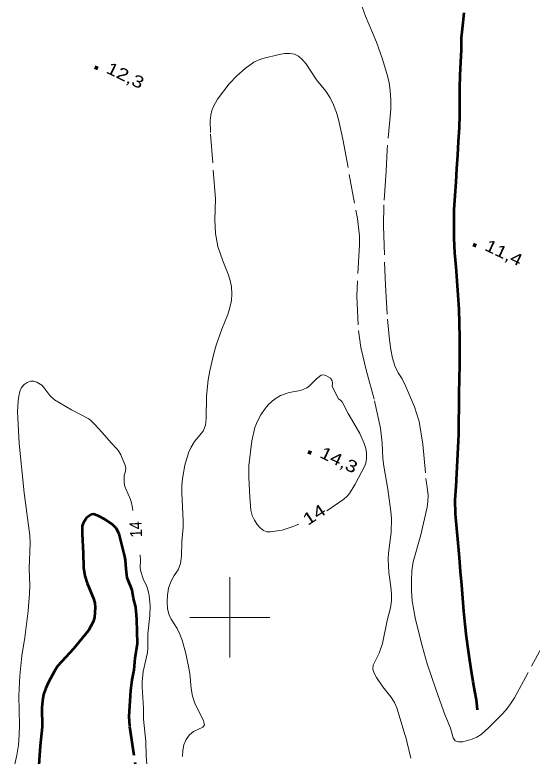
# Model space of a CAD drawing. Extents: x 355726 to 357533, y 5103782 to 5105258.
# Drawn here: x 356273.2 to 356337.7, y 5104282.7 to 5104375.1 of the extents above; entities that cross this region are included whole.
import ezdxf
from ezdxf.enums import TextEntityAlignment as Align

# ---------------------------------------------------------------- set-up
doc = ezdxf.new("R2010")
doc.units = 0
doc.header["$LTSCALE"] = 0.6
doc.linetypes.add('DASH_DOUBLE_DOT', pattern=[9.2, 5, -1.2, 0.3, -1.2, 0.3, -1.2])
doc.linetypes.add('LONG_DASHED', pattern=[7.5, 6, -1.5])
for name, color, linetype, lineweight in [('1', 7, 'LONG_DASHED', 53), ('2', 7, 'LONG_DASHED', 13), ('3', 7, 'Continuous', 140), ('4', 7, 'DASH_DOUBLE_DOT', 53), ('61', 7, 'Continuous', 13)]:
    doc.layers.add(name, color=color, linetype=linetype, lineweight=lineweight)

msp = doc.modelspace()

# ---------------------------------------------------------------- linework, layer by layer
at = {"layer": '1'}
msp.add_lwpolyline([(356288.76, 5104278.34), (356287.53, 5104286.45), (356287.46, 5104287.66), (356287.66, 5104290.91), (356287.84, 5104292.21), (356288.09, 5104293.46), (356288.22, 5104294.91), (356288.47, 5104296.76), (356288.42, 5104299.73), (356288.3, 5104301.28), (356287.98, 5104302.36), (356287.81, 5104303.38), (356287.22, 5104304.95), (356287.06, 5104306.05), (356287, 5104307.12), (356286.93, 5104307.59), (356286.2, 5104310.44), (356285.82, 5104311.13), (356285.33, 5104311.61), (356284.38, 5104312.25), (356283.58, 5104312.68), (356283, 5104312.88), (356282.72, 5104312.83), (356282.13, 5104312.41), (356281.71, 5104311.75), (356281.6, 5104311.38), (356281.57, 5104310.4), (356281.71, 5104308), (356281.74, 5104306.22), (356281.94, 5104305.18), (356282.22, 5104304.26), (356283.02, 5104302.34), (356283.15, 5104301.82), (356283.22, 5104301.24), (356283.12, 5104300.01), (356282.95, 5104299.43), (356282.36, 5104298.38), (356280.5, 5104296.09), (356278.52, 5104293.94), (356278.12, 5104293.32), (356277.37, 5104291.94), (356277.04, 5104291.19), (356276.78, 5104290.4), (356276.63, 5104289.59), (356276.57, 5104288.74), (356276.6, 5104286.38), (356276.37, 5104284), (356275.85, 5104277.04)], dxfattribs=at)
at = {"layer": '2'}
for points in [[(356316.53, 5104376.09), (356316.91, 5104374.96), (356318.28, 5104371.69), (356319.03, 5104369.59), (356319.62, 5104367.63), (356319.86, 5104366.67), (356320.02, 5104365.63), (356320.1, 5104364.53), (356320.08, 5104363.34), (356319.61, 5104358.26), (356319.5, 5104355.61), (356319.22, 5104351.44), (356319.16, 5104348.8), (356319.41, 5104341.4), (356319.65, 5104337.17), (356319.92, 5104334.59), (356320.09, 5104333.41), (356320.31, 5104332.33), (356320.6, 5104331.36), (356321.02, 5104330.5), (356321.49, 5104329.73), (356321.93, 5104328.88), (356323.03, 5104326.24), (356323.61, 5104324.43), (356324.08, 5104321.61), (356324.47, 5104317.32), (356324.68, 5104315.92), (356324.74, 5104315.2), (356324.72, 5104314.47), (356324.6, 5104313.74), (356323.82, 5104310.3), (356322.89, 5104306.93), (356322.71, 5104305.8)], [(356294.12, 5104282.68), (356294.15, 5104283.4), (356294.29, 5104284.13), (356294.57, 5104284.79), (356294.96, 5104285.37), (356295.48, 5104285.8), (356296.62, 5104286.3), (356296.83, 5104286.63), (356296.72, 5104287.13), (356295.64, 5104289.32), (356295.35, 5104290.2), (356295.18, 5104291.16), (356295, 5104293.03), (356294.86, 5104293.88), (356294.51, 5104295.51), (356294.06, 5104297.15), (356293.78, 5104297.93), (356293.45, 5104298.63), (356292.69, 5104299.8), (356292.4, 5104300.41), (356292.25, 5104301.13), (356292.19, 5104301.93), (356292.24, 5104302.76), (356292.36, 5104303.63), (356292.64, 5104304.44), (356293.05, 5104305.21), (356293.55, 5104305.93), (356293.86, 5104306.74), (356293.96, 5104307.63), (356294.04, 5104309.46), (356294.19, 5104311.19), (356294.2, 5104312.03), (356294, 5104315.55), (356294, 5104316.44), (356294.1, 5104317.3), (356294.41, 5104318.97), (356294.86, 5104320.5), (356295.18, 5104321.24), (356295.62, 5104321.93), (356296.66, 5104323.21), (356296.98, 5104323.96), (356297.05, 5104324.8), (356297.09, 5104327.59), (356297.32, 5104329.63), (356297.52, 5104330.74), (356298.02, 5104332.9), (356298.32, 5104333.93), (356299.02, 5104335.94), (356299.74, 5104337.74), (356300.01, 5104338.62), (356300.21, 5104339.49), (356300.26, 5104340.33), (356300.22, 5104341.19), (356300.05, 5104342.01), (356299.81, 5104342.8), (356299.13, 5104344.43), (356298.52, 5104346.22), (356298.2, 5104347.86), (356298.15, 5104349.55), (356298.21, 5104352.17), (356297.6, 5104360.43), (356297.57, 5104361.93), (356297.62, 5104362.59), (356297.76, 5104363.18), (356297.97, 5104363.7), (356298.45, 5104364.59), (356299.91, 5104366.5), (356300.86, 5104367.49), (356301.93, 5104368.43), (356302.98, 5104369.21), (356303.53, 5104369.47), (356304.14, 5104369.68), (356306.17, 5104370.18), (356306.84, 5104370.28), (356307.47, 5104370.3)], [(356307.47, 5104370.3), (356308.06, 5104370.22), (356308.57, 5104369.97), (356309.04, 5104369.55), (356309.48, 5104369.04), (356310.82, 5104367.01), (356312, 5104365.59), (356312.51, 5104364.76), (356312.95, 5104363.88), (356313.32, 5104362.93), (356313.61, 5104361.88), (356314.09, 5104359.62), (356315.92, 5104349.73), (356316.16, 5104347.51), (356316.19, 5104346.46), (356315.83, 5104340.05), (356316.04, 5104335.76), (356316.34, 5104333.63), (356317.06, 5104330.7), (356318.06, 5104326.98), (356318.79, 5104323.57), (356319.01, 5104321.74), (356319.07, 5104319.83), (356319.2, 5104318.87), (356319.71, 5104316), (356320.1, 5104313.22), (356320.17, 5104312.32), (356320.14, 5104310.58), (356319.78, 5104308.03), (356319.75, 5104307.25), (356319.85, 5104305.59), (356320.09, 5104303.8), (356320.16, 5104302.91), (356320.15, 5104302.05), (356320.04, 5104301.2), (356319.63, 5104299.61), (356319.04, 5104296.74), (356318.63, 5104295.55), (356317.89, 5104294.03), (356317.84, 5104293.55), (356317.99, 5104293.04), (356318.28, 5104292.5), (356319.07, 5104291.36), (356320.07, 5104290.11), (356320.53, 5104289.41), (356320.85, 5104288.73), (356321.91, 5104285.23), (356322.58, 5104282.45)], [(356322.71, 5104305.8), (356322.65, 5104304.58), (356322.66, 5104303.32), (356322.76, 5104302.07), (356323.15, 5104299.74), (356323.98, 5104296.46), (356324.63, 5104294.21), (356325.68, 5104291.05), (356326.93, 5104287.61), (356327.51, 5104286.19), (356327.88, 5104284.98), (356328.13, 5104284.63), (356328.53, 5104284.5), (356329.06, 5104284.51), (356330.25, 5104284.84), (356330.81, 5104285.08), (356331.35, 5104285.41), (356332.31, 5104286.26), (356333.9, 5104287.86), (356334.46, 5104288.5), (356335.01, 5104289.22), (356335.5, 5104289.96), (356339.13, 5104296.66)]]:
    msp.add_lwpolyline(points, dxfattribs=at)
at = {"layer": '2', "linetype": 'Continuous'}
for points in [[(356308.6, 5104311.63), (356307.66, 5104311.23), (356306.54, 5104310.86), (356305.09, 5104310.65), (356304.62, 5104310.66), (356304.2, 5104310.84), (356303.79, 5104311.15), (356303.42, 5104311.59), (356303.07, 5104312.13), (356302.81, 5104312.72), (356302.64, 5104313.38), (356302.5, 5104314.97), (356302.37, 5104317.44), (356302.39, 5104318.95), (356302.74, 5104322.03), (356303.13, 5104323.68), (356303.47, 5104324.48), (356303.88, 5104325.25), (356304.34, 5104325.92), (356304.8, 5104326.48), (356305.29, 5104326.96), (356305.8, 5104327.34), (356306.33, 5104327.65), (356307.4, 5104328.03), (356308.84, 5104328.3), (356309.25, 5104328.44), (356309.62, 5104328.63), (356309.95, 5104328.86), (356310.81, 5104329.72), (356311.4, 5104330.18), (356311.7, 5104330.23), (356311.96, 5104330.15), (356312.56, 5104329.82), (356312.79, 5104329.51), (356312.82, 5104329.26), (356312.79, 5104328.8), (356313.56, 5104327.24), (356313.82, 5104327.09), (356314.01, 5104326.87), (356314.75, 5104325.43), (356315.49, 5104324.22), (356316.2, 5104322.93), (356316.75, 5104321.67), (356316.96, 5104321.05), (356317.04, 5104320.47), (356317.06, 5104319.9), (356317, 5104319.38), (356316.85, 5104318.91), (356315.63, 5104316.59), (356314.92, 5104315.45), (356314.6, 5104315.09), (356314.21, 5104314.76), (356312.1, 5104313.3)], [(356287.92, 5104313.32), (356287.79, 5104314.13), (356287.63, 5104314.7), (356287.02, 5104316.01), (356286.88, 5104316.45), (356286.81, 5104316.9), (356286.82, 5104317.69), (356286.99, 5104318.21), (356287.03, 5104318.62), (356286.92, 5104319.05), (356286.41, 5104320.26), (356286.12, 5104320.78), (356285.92, 5104321.03), (356285.19, 5104321.75), (356284.09, 5104323.05), (356283.16, 5104324.04), (356282.57, 5104324.62), (356282.33, 5104324.79), (356280.25, 5104325.88), (356278.14, 5104327.13), (356277.54, 5104327.67), (356276.82, 5104328.68), (356276.56, 5104328.96), (356275.93, 5104329.34), (356275.58, 5104329.46), (356275.16, 5104329.45), (356274.73, 5104329.3), (356274.34, 5104329.04), (356274.03, 5104328.66), (356273.82, 5104328.16), (356273.68, 5104327.58), (356273.6, 5104326.98), (356273.53, 5104325.62), (356273.55, 5104324.88), (356273.75, 5104321.7), (356274.34, 5104315.51), (356275.07, 5104310.23), (356275.1, 5104309.24), (356275, 5104306.08), (356275.05, 5104304.03), (356275.03, 5104302.99), (356274.87, 5104300.84), (356274.45, 5104297.51), (356274.08, 5104295.21), (356273.83, 5104292.74), (356273.7, 5104290.23), (356273.76, 5104286.58), (356273.74, 5104285.37), (356273.65, 5104284.09), (356273.45, 5104282.84), (356273.19, 5104281.69)], [(356289.66, 5104281.65), (356289.57, 5104282.75), (356289.51, 5104284.55), (356289.24, 5104287.3), (356289.22, 5104288.67), (356289.06, 5104291.33), (356289.07, 5104291.98), (356289.18, 5104293.26), (356289.73, 5104295.62), (356289.77, 5104296.17), (356289.76, 5104297.96), (356290.01, 5104300.26), (356290.07, 5104301.43), (356289.96, 5104302.73), (356289.83, 5104303.3), (356289.64, 5104303.84), (356289.18, 5104304.8), (356288.89, 5104305.73), (356288.82, 5104306.18), (356288.85, 5104307.13), (356288.81, 5104307.82)]]:
    msp.add_lwpolyline(points, dxfattribs=at)
at = {"layer": '3'}
for p, q in [((356283.17, 5104368.58), (356283.53, 5104368.41)), ((356330.36, 5104346.48), (356330.72, 5104346.31)), ((356309.79, 5104320.65), (356310.15, 5104320.48))]:
    msp.add_line(p, q, dxfattribs=at)
at = {"layer": '4'}
msp.add_lwpolyline([(356330.9, 5104288.47), (356330.85, 5104288.95), (356330.75, 5104289.74), (356330.56, 5104290.8), (356330.36, 5104291.98), (356330.16, 5104293.26), (356329.92, 5104294.63), (356329.74, 5104296.07), (356329.52, 5104297.58), (356329.36, 5104299.13), (356329.21, 5104300.76), (356329.05, 5104302.38), (356328.94, 5104304.01), (356328.79, 5104305.72), (356328.64, 5104307.49), (356328.5, 5104309.3), (356328.31, 5104311.09), (356328.16, 5104312.9), (356328.12, 5104314.65), (356328.22, 5104316.33), (356328.32, 5104317.94), (356328.42, 5104319.55), (356328.47, 5104321.18), (356328.55, 5104322.84), (356328.58, 5104324.48), (356328.59, 5104326.18), (356328.61, 5104327.92), (356328.66, 5104329.73), (356328.71, 5104331.5), (356328.7, 5104333.22), (356328.69, 5104334.92), (356328.67, 5104336.65), (356328.62, 5104338.41), (356328.5, 5104340.17), (356328.38, 5104341.95), (356328.23, 5104343.68), (356328.07, 5104345.46), (356327.98, 5104347.26), (356327.98, 5104349.05), (356327.99, 5104350.82), (356328.11, 5104352.58), (356328.22, 5104354.26), (356328.32, 5104355.96), (356328.43, 5104357.61), (356328.54, 5104359.32), (356328.63, 5104361.03), (356328.7, 5104362.7), (356328.7, 5104364.33), (356328.7, 5104365.96), (356328.75, 5104367.59), (356328.82, 5104369.2), (356328.88, 5104370.76), (356328.91, 5104372.24), (356329.05, 5104373.76), (356329.22, 5104375.38)], dxfattribs=at)
at = {"layer": '61'}
for p, q in [((356300, 5104295), (356300, 5104305)), ((356295, 5104300), (356305, 5104300))]:
    msp.add_line(p, q, dxfattribs=at)

# ---------------------------------------------------------------- texts
at = {"layer": '2'}
for rotation, width, p in [(33.486, 1.3, (356310.936, 5104312.191)), (92.98, 0.9, (356289.028, 5104311.016))]:
    msp.add_text('14', height=1.5, rotation=rotation, dxfattribs=dict(at, width=width)).set_placement(p, align=Align.CENTER)
at = {"layer": '3', "width": 1.25}
for s, p in [('12,3   ', (356284.45, 5104367.94)), ('11,4   ', (356331.65, 5104345.84)), ('14,3   ', (356311.08, 5104320.01))]:
    msp.add_text(s, height=1.5, rotation=334.423, dxfattribs=at).set_placement(p)

doc.saveas('drawing.dxf')
